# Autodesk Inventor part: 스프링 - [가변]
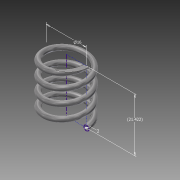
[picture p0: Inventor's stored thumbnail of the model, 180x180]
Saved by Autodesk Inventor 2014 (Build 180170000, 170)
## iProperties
Created: 2015-04
Part Number: 스프링 - [가변]
Material: 강철, 탄소
Document SubType Name: Modeling
Designer: basic
Mass: 4.88317 g
Surface Area: 12.6362 cm^2
Volume: 0.620479 cm^3
Density: 7.87 g/cm^3
Appearance: 반연마
Author: basic
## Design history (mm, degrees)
sketch "스케치1"
  geometry: L1 (0, 0)-(-8, 0); L2 (-8, 0)-(-8, 21.422); L3 (-8, 21.422)-(0, 21.422); L4 (0, 21.422)-(0, 0); C1 r 1 at (-8, 0)
  constraints: 8 end point, 2 parallel, 1 centre point, 1 coincident, 1 horizontal, 1 perpendicular
  dimensions: "d0" = 2 diameter of C1; "d1" = 21.42196 distance between parallel lines of L1 L3 (derived); "d2" = 16 diameter of L2 L4
feature "코일1" sketch "스케치1" pitch "d3" = 10; turns "d5" = 4; dims "d4" = 21.42196 (= d1), "d6" = 0, angle "d7" = 90 deg, angle "d8" = 90 deg, "d9" = 0, "d10" = 0
sketch "스케치2"
  geometry: L1 (9, 0)-(7, 0) reference; 1 further point
  constraints: 1 horizontal alignment
extrude "돌출1" cut sketch "스케치2" distance "d11" = 10; taper "d12" = 0 deg
node "작업 평면1"
sketch "스케치3"
  geometry: L1 (1, 0)-(-1, 0) reference; 1 further point
  constraints: 1 horizontal alignment
extrude "돌출2" cut sketch "스케치3" distance "d14" = 10; taper "d15" = 0 deg
node "솔리드1"
node "절단 모서리 투영1"
node "절단 모서리 투영2"
other parameters: "d13" = 0
